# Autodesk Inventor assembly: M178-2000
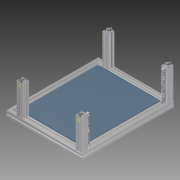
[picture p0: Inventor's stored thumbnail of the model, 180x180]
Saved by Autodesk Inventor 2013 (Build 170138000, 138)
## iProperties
Created: 2004-11
Part Number: M178-2000
Document SubType Name: Assembly
Designer: Autodesk, Inc.
Manufacturer: Standard
Standards Organization: Custom
Mass: 6108.1 g
Surface Area: 20444.7 cm^2
Volume: 3295.53 cm^3
Density: 1.85345 g/cm^3
CAGE: 1LJX3
Dept. ID: Product Design
Description #2: ---
Finish #1: ---
Finish #2: ---
Material ID: ---
Project Number: ---
Author: Autodesk, Inc.
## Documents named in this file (16)
- Z:\_DATEN\Test Station\Components\M178-2000.iam
- Z:\_DATEN\Test Station\Components\M178-2001.ipt
- Z:\_DATEN\Test Station\Components\22-100.ipt
- Z:\_DATEN\Test Station\Components\20-004.iam
- Z:\_DATEN\Test Station\Components\M178-2002-01.ipt
- Z:\_DATEN\Test Station\Components\M178-2002-02.ipt
- Z:\_DATEN\Test Station\Components\M178-2005.ipt
- Z:\_DATEN\Test Station\Components\M178-2000-Base_Phantom.iam
- Z:\_DATEN\Test Station\Components\20-075.ipt
- Z:\_DATEN\Test Station\Components\24-506-6F.ipt
- Z:\_DATEN\Test Station\Components\24-230-6.ipt
- C:\Users\kelleyb.ADS\Desktop\Samples MIGRATED 2009 224 RTM_1\Standard Parts\Test Station Content\Extrusions\Rack Angle (19in).ipt
- C:\Users\kelleyb.ADS\Desktop\Samples MIGRATED 2009 224 RTM_1\Standard Parts\Test Station Content\Extrusions\40 Series Profiles.ipt
- C:\Users\kelleyb.ADS\Desktop\Samples MIGRATED 2009 224 RTM_1\Standard Parts\Test Station Content\Fastners\20-07X Clip Nut.ipt
- C:\Users\kelleyb.ADS\Desktop\Samples MIGRATED 2009 224 RTM_1\Standard Parts\Test Station Content\Fastners\24-5XX-YY Setscrews.ipt
- C:\Users\kelleyb.ADS\Desktop\Samples MIGRATED 2009 224 RTM_1\Standard Parts\Test Station Content\Fastners\2X-YYY-ZZ IPS Screws.ipt
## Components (37 placed, 10 different names)
1. M178-2001:1 — Flush:2, Mate:2, Flush:3, Mate:11, Insert:6, Insert:7
2. M178-2001:2 — Flush:1, Mate:2, Flush:3, Mate:3, Flush:4, Mate:4, Mate:5, Mate:10, Angle:1, Insert:4, Insert:5, Mate:19, Mate:8, Mate:9
3. M178-2000-Base_Phantom:1 [sub-assembly] — Mate:12, Flush:7, Flush:8, Flush:9, Mate:13, Mate:15, Mate:16, Mate:17, Mate:18
4. M178-2000-Base_Phantom:2 [sub-assembly] — Flush:9, Mate:13, Flush:10, Mate:14, Flush:11
5. 24-506-6F:1 — Insert:5
6. 24-506-6F:2 — Insert:4
7. 24-506-6F:3 — Insert:7
8. 24-506-6F:4 — Insert:6
9. M178-2005:1 — Flush:14, Mate:17, Mate:18, Insert:8, Insert:9, Insert:10, Insert:11
10. 24-230-6:1 — Insert:9
11. 24-230-6:2 — Insert:8
12. 24-230-6:3 — Insert:10
13. 24-230-6:4 — Insert:11
14. 20-075:2 — Flush:15, Flush:16, Mate:19
15. 20-075:1 — Mate:10, Angle:1, Flush:15, Flush:16, Mate:8, Mate:9
16. 20-075:3
17. 20-075:6
18. 20-075:4
19. 20-075:7
20. 20-075:5
21. 20-075:8
22. M178-2002-01:1 — Flush:4, Mate:4, Mate:5, Flush:5, Flush:6, Insert:1, Angle:3, Mate:12, Flush:7, Flush:8, Insert:3, Angle:4
23. 20-004:1 [sub-assembly] — Insert:1, Angle:3
24. M178-2002-02:4 — Flush:5, Flush:6, Mate:11, Insert:2, Angle:2, Flush:10
25. 20-004:2 [sub-assembly] — Insert:2, Angle:2
26. M178-2002-01:3
27. 20-004:3 [sub-assembly]
28. M178-2002-02:2
29. 20-004:4 [sub-assembly]
30. 20-004:5 [sub-assembly] — Insert:3, Angle:4
31. 20-004:6 [sub-assembly]
32. 20-004:7 [sub-assembly]
33. 20-004:8 [sub-assembly]
34. 22-100:1 — Mate:14, Mate:15, Flush:11, Flush:12, Flush:13
35. 22-100:2 — Mate:16, Flush:12, Flush:13
36. 22-100:3 — Flush:14
37. 22-100:4
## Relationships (47: Flush 16, Mate 16, Insert 11, Angle 4)
- Flush:1: M178-2001:2
- Flush:2: M178-2001:1
- Mate:2: M178-2001:1 ↔ M178-2001:2
- Flush:3: M178-2001:1 ↔ M178-2001:2
- Mate:3: M178-2001:2
- Flush:4: M178-2001:2 ↔ M178-2002-01:1
- Mate:4: M178-2001:2 ↔ M178-2002-01:1
- Mate:5: M178-2001:2 ↔ M178-2002-01:1
- Mate:10: M178-2001:2 ↔ 20-075:1
- Angle:1: M178-2001:2 ↔ 20-075:1
- Flush:5: M178-2002-01:1 ↔ M178-2002-02:4
- Flush:6: M178-2002-01:1 ↔ M178-2002-02:4
- Mate:11: M178-2001:1 ↔ M178-2002-02:4
- Insert:1: M178-2002-01:1 ↔ 20-004:1
- Insert:2: M178-2002-02:4 ↔ 20-004:2
- Angle:2: M178-2002-02:4 ↔ 20-004:2
- Angle:3: M178-2002-01:1 ↔ 20-004:1
- Mate:12: M178-2000-Base_Phantom:1 ↔ M178-2002-01:1
- Flush:7: M178-2000-Base_Phantom:1 ↔ M178-2002-01:1
- Flush:8: M178-2000-Base_Phantom:1 ↔ M178-2002-01:1
- Flush:9: M178-2000-Base_Phantom:1 ↔ M178-2000-Base_Phantom:2
- Mate:13: M178-2000-Base_Phantom:1 ↔ M178-2000-Base_Phantom:2
- Flush:10: M178-2000-Base_Phantom:2 ↔ M178-2002-02:4
- Insert:3: M178-2002-01:1 ↔ 20-004:5
- Angle:4: M178-2002-01:1 ↔ 20-004:5
- Insert:4: M178-2001:2 ↔ 24-506-6F:2
- Insert:5: M178-2001:2 ↔ 24-506-6F:1
- Insert:6: M178-2001:1 ↔ 24-506-6F:4
- Insert:7: M178-2001:1 ↔ 24-506-6F:3
- Mate:14: M178-2000-Base_Phantom:2 ↔ 22-100:1
- Mate:15: M178-2000-Base_Phantom:1 ↔ 22-100:1
- Flush:11: M178-2000-Base_Phantom:2 ↔ 22-100:1
- Mate:16: M178-2000-Base_Phantom:1 ↔ 22-100:2
- Flush:12: 22-100:1 ↔ 22-100:2
- Flush:13: 22-100:1 ↔ 22-100:2
- Flush:14: M178-2005:1 ↔ 22-100:3
- Mate:17: M178-2000-Base_Phantom:1 ↔ M178-2005:1
- Mate:18: M178-2000-Base_Phantom:1 ↔ M178-2005:1
- Insert:8: M178-2005:1 ↔ 24-230-6:2
- Insert:9: M178-2005:1 ↔ 24-230-6:1
- Insert:10: M178-2005:1 ↔ 24-230-6:3
- Insert:11: M178-2005:1 ↔ 24-230-6:4
- Flush:15: 20-075:2 ↔ 20-075:1
- Flush:16: 20-075:2 ↔ 20-075:1
- Mate:19: M178-2001:2 ↔ 20-075:2
- Mate:8: M178-2001:2 ↔ 20-075:1
- Mate:9: M178-2001:2 ↔ 20-075:1
